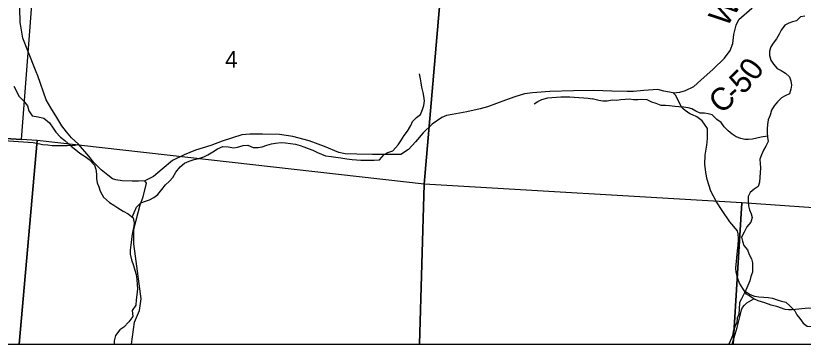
# Model space of a CAD drawing. Extents: x 5.6 to 39.6, y 0.7 to 22.7.
# Drawn here: x 9.058 to 11.039, y 14.907 to 15.732 of the extents above; entities that cross this region are included whole.
import ezdxf

# ---------------------------------------------------------------- set-up
doc = ezdxf.new("R2010")
doc.units = 0
doc.layers.add('Default', color=7, linetype='Continuous')

msp = doc.modelspace()

# ---------------------------------------------------------------- linework, layer by layer
at = {"layer": 'Default'}
for p, q in [((9.0666, 14.9074), (10.0736, 14.9074)), ((10.0736, 14.9074), (10.8627, 14.9074)), ((10.8627, 14.9074), (11.8881, 14.9074))]:
    msp.add_line(p, q, dxfattribs=at)
for points in [[(8.2518, 18.5322), (8.2518, 14.9074), (15.0518, 14.9074), (15.0518, 18.0251)], [(8.2518, 18.5322), (8.2518, 14.9074), (15.0518, 14.9074), (15.0518, 18.0251)], [(8.2518, 18.5322), (8.2518, 14.9074), (15.0518, 14.9074), (15.0518, 18.0251)], [(9.071, 15.7062), (9.0694, 15.7157), (9.0678, 15.751), (9.0715, 15.7916), (9.0832, 15.8235), (9.0994, 15.8528), (9.1107, 15.8684), (9.2839, 16.1036), (9.2922, 16.1192), (9.2982, 16.1355), (9.3024, 16.1522), (9.2985, 16.1818), (9.2893, 16.2016), (9.2741, 16.2247), (9.1605, 16.3581), (9.0759, 16.4554)], [(8.2518, 15.7856), (8.2639, 15.7623), (8.2659, 15.4721), (9.0725, 15.4217), (9.1174, 16.0112), (9.0418, 16.1995), (9.0049, 16.4106), (8.3039, 16.4383), (8.2518, 16.391)], [(10.7121, 15.5385), (10.7289, 15.5406), (10.7424, 15.5448), (10.764, 15.5548), (10.7815, 15.5703), (10.8123, 15.5978), (10.8409, 15.6257), (10.8554, 15.6454), (10.862, 15.6628), (10.8647, 15.6856), (10.8702, 15.7091), (10.8771, 15.7227), (10.9094, 15.751), (10.9487, 15.7883), (10.9807, 15.8204), (11.0062, 15.8514), (11.0204, 15.874), (11.0319, 15.8941), (11.0411, 15.9233)], [(11.0426, 15.731), (11.0319, 15.7294), (11.0223, 15.7197), (11.012, 15.7173), (11.0024, 15.7137), (10.9929, 15.709), (10.9831, 15.6959), (10.9783, 15.6858)], [(9.1097, 15.5912), (9.0885, 15.6446), (9.076, 15.6762), (9.071, 15.7062)], [(10.9783, 15.6858), (10.9716, 15.6742), (10.9634, 15.6638), (10.9572, 15.654), (10.9543, 15.6435), (10.954, 15.6325), (10.9576, 15.6206), (10.9641, 15.6106), (10.973, 15.6002), (10.9831, 15.5947), (10.9943, 15.588), (11.004, 15.5787), (11.0079, 15.5691), (11.0095, 15.558), (11.0074, 15.5479), (11.0045, 15.5365), (10.9938, 15.5311), (10.9842, 15.5264), (10.9742, 15.5164), (10.966, 15.5059), (10.9593, 15.4954), (10.9556, 15.4826), (10.9508, 15.4706), (10.9494, 15.4596), (10.948, 15.4483), (10.9482, 15.4384), (10.9494, 15.4274), (10.9503, 15.4164), (10.9451, 15.4051), (10.9389, 15.395), (10.9337, 15.3834), (10.9296, 15.3721), (10.9309, 15.3603), (10.931, 15.35), (10.9304, 15.3375), (10.9294, 15.3266), (10.9291, 15.3141), (10.9258, 15.3039), (10.9155, 15.2969), (10.9054, 15.2884), (10.9006, 15.2783), (10.9008, 15.2669), (10.9016, 15.2551), (10.9041, 15.2452), (10.908, 15.2349), (10.9101, 15.2253), (10.9068, 15.214), (10.897, 15.2021), (10.8907, 15.189), (10.884, 15.1766), (10.8864, 15.1663), (10.8899, 15.1556), (10.8984, 15.1441), (10.9031, 15.1326), (10.9085, 15.1218), (10.9113, 15.1115), (10.9114, 15.1009), (10.9112, 15.0884), (10.9075, 15.0775), (10.9042, 15.0669), (10.8994, 15.0545), (10.8946, 15.0433), (10.8887, 15.0312), (10.8835, 15.0215), (10.8784, 15.0118), (10.878, 14.9957)], [(9.2414, 15.3798), (9.216, 15.4099), (9.1982, 15.4258), (9.1853, 15.4408), (9.1742, 15.4562), (9.1616, 15.4767), (9.146, 15.5009), (9.1345, 15.5214), (9.1136, 15.5813), (9.1097, 15.5912)], [(9.351, 15.2267), (9.3562, 15.238), (9.362, 15.2516), (9.3723, 15.2621), (9.3845, 15.2665), (9.3948, 15.2702), (9.4055, 15.2761), (9.4154, 15.2832), (9.4258, 15.2956), (9.435, 15.3076), (9.4446, 15.3166), (9.4534, 15.3264), (9.4608, 15.3392), (9.4715, 15.3528), (9.4822, 15.3617), (9.4941, 15.3669), (9.5066, 15.3713), (9.5188, 15.3742), (9.5313, 15.3779), (9.5412, 15.3827), (9.5534, 15.3902), (9.5657, 15.3984), (9.5786, 15.4043), (9.5922, 15.4034), (9.6066, 15.4005), (9.6161, 15.402), (9.6298, 15.4067), (9.6419, 15.4073), (9.6555, 15.4011), (9.6676, 15.4014), (9.6779, 15.4035), (9.6897, 15.4076), (9.7011, 15.4108), (9.7113, 15.4126), (9.7258, 15.4136), (9.7367, 15.4135), (9.7489, 15.4118), (9.7613, 15.4098), (9.773, 15.4066), (9.7829, 15.4031), (9.7938, 15.3991), (9.8051, 15.3945), (9.8172, 15.3886), (9.827, 15.3851), (9.8368, 15.3808), (9.8516, 15.3787), (9.8629, 15.3775), (9.8758, 15.3758), (9.8905, 15.3734), (9.9038, 15.3713), (9.9155, 15.3704), (9.9261, 15.3699), (9.9504, 15.3696), (9.9598, 15.3699), (9.9731, 15.3709), (9.9846, 15.384), (9.9942, 15.3885), (10.0063, 15.3933), (10.0198, 15.4079), (10.0263, 15.4181), (10.0348, 15.4313), (10.0433, 15.4426), (10.0518, 15.4569), (10.0557, 15.4667), (10.0664, 15.4772), (10.076, 15.4843), (10.0814, 15.4971), (10.0849, 15.507), (10.0858, 15.5184), (10.0841, 15.5301), (10.0827, 15.54), (10.0798, 15.5526), (10.078, 15.564), (10.0762, 15.5742), (10.0737, 15.5864)], [(9.0528, 15.5557), (9.0587, 15.5446), (9.0654, 15.5305), (9.0774, 15.5186), (9.0879, 15.506), (9.0911, 15.4938), (9.099, 15.4812), (9.1145, 15.4783), (9.1288, 15.4748), (9.1427, 15.4632), (9.152, 15.4502), (9.1587, 15.4399), (9.1703, 15.4276), (9.1812, 15.4191), (9.1974, 15.4049), (9.2094, 15.3953), (9.2195, 15.3876), (9.2323, 15.3791), (9.2425, 15.371), (9.2563, 15.3575), (9.2596, 15.3469), (9.261, 15.3343), (9.2613, 15.3233), (9.263, 15.313), (9.2667, 15.3024), (9.2707, 15.2921), (9.2785, 15.2764), (9.2935, 15.2634), (9.3045, 15.2564), (9.315, 15.2498), (9.3285, 15.2417), (9.341, 15.2347), (9.353, 15.2251), (9.3562, 15.2125), (9.3546, 15.2027), (9.3522, 15.1921), (9.3498, 15.1788), (9.3489, 15.1694), (9.3477, 15.1568), (9.3456, 15.144), (9.3459, 15.1333), (9.3491, 15.1193), (9.3543, 15.1052), (9.3579, 15.0934), (9.3605, 15.0823), (9.3626, 15.0694), (9.3636, 15.0572), (9.3638, 15.0466), (9.3629, 15.0318), (9.3612, 15.0189), (9.36, 15.0053)], [(10.8747, 15.1502), (10.8752, 15.1546), (10.8757, 15.1729), (10.8749, 15.1848), (10.8734, 15.1923), (10.8541, 15.2144), (10.8348, 15.2431), (10.8209, 15.2652), (10.8064, 15.2919), (10.7973, 15.3211), (10.794, 15.3387), (10.7914, 15.3598), (10.7924, 15.3824), (10.7962, 15.4076), (10.7983, 15.4242), (10.7978, 15.4493), (10.7849, 15.4684), (10.7715, 15.4787), (10.7605, 15.4835), (10.7536, 15.4858), (10.7415, 15.4941), (10.7372, 15.4986), (10.7326, 15.5029), (10.7241, 15.5205), (10.7179, 15.5328), (10.7121, 15.5385), (10.6879, 15.5431), (10.6731, 15.5469), (10.638, 15.5446), (10.6117, 15.5419), (10.5956, 15.5419), (10.5573, 15.5429), (10.512, 15.5449), (10.4609, 15.5434), (10.4014, 15.5421), (10.3582, 15.5389), (10.3381, 15.5364), (10.3137, 15.5291), (10.2898, 15.5203), (10.2444, 15.5034), (10.2262, 15.4986), (10.193, 15.4908), (10.1554, 15.4843), (10.1417, 15.4815), (10.1296, 15.4765), (10.1058, 15.4602), (10.0827, 15.4381), (10.0634, 15.4157), (10.046, 15.3966), (10.0266, 15.3837), (9.9912, 15.3842), (9.9552, 15.3842), (9.9158, 15.385), (9.8869, 15.3855), (9.8705, 15.3893), (9.8343, 15.4041), (9.796, 15.4182), (9.7551, 15.4295), (9.7218, 15.434), (9.6787, 15.435), (9.647, 15.435), (9.6264, 15.4333), (9.5768, 15.4172), (9.549, 15.4063), (9.51, 15.3944), (9.4817, 15.383), (9.452, 15.3684), (9.4266, 15.3467), (9.4043, 15.3285), (9.383, 15.3174), (9.3671, 15.3173), (9.3508, 15.3173), (9.3258, 15.3176), (9.3097, 15.3201), (9.3017, 15.3231), (9.2892, 15.3323), (9.2732, 15.3456), (9.2546, 15.3641), (9.2414, 15.3798)], [(10.362, 15.5114), (10.3716, 15.517), (10.3811, 15.5222), (10.3963, 15.5262), (10.4065, 15.5272), (10.4183, 15.5282), (10.4289, 15.5284), (10.441, 15.5291), (10.4517, 15.5289), (10.4626, 15.528), (10.474, 15.5272), (10.4872, 15.5262), (10.4978, 15.5254), (10.5077, 15.5241)], [(10.9491, 15.43), (10.9335, 15.4274), (10.9225, 15.4246), (10.9115, 15.4225), (10.9016, 15.4216), (10.8917, 15.4218), (10.8816, 15.4243), (10.8703, 15.4284), (10.8598, 15.4351), (10.8498, 15.4433), (10.8402, 15.453), (10.8321, 15.4641), (10.8213, 15.472), (10.8098, 15.4832), (10.8, 15.4861), (10.7902, 15.4874), (10.78, 15.4873), (10.7687, 15.4925), (10.759, 15.4988), (10.7492, 15.5013), (10.7379, 15.503), (10.7258, 15.504), (10.7156, 15.5047), (10.7024, 15.5061), (10.6925, 15.5071), (10.6812, 15.5066), (10.6688, 15.5121), (10.6579, 15.5154), (10.6463, 15.521), (10.6357, 15.5224), (10.6228, 15.5215), (10.6118, 15.521), (10.6009, 15.5228), (10.5906, 15.5218), (10.5804, 15.5213), (10.5694, 15.5197), (10.558, 15.5207), (10.5455, 15.5175), (10.5345, 15.5178), (10.5247, 15.5195), (10.515, 15.5221), (10.5077, 15.5241)], [(9.0666, 14.9074), (9.1119, 15.4192), (9.0725, 15.4217), (8.2659, 15.4721), (8.2518, 15.4436)], [(8.2518, 15.4436), (8.2518, 14.9074), (9.0666, 14.9074)], [(8.967, 15.4233), (9.1014, 15.4139), (9.1188, 15.4104), (9.1255, 15.4092), (9.1387, 15.4082), (9.1497, 15.4066), (9.1562, 15.4066)], [(10.0736, 14.9074), (10.0852, 15.3096), (9.1119, 15.4192), (9.0666, 14.9074)], [(9.1562, 15.4066), (9.1582, 15.4066), (9.1692, 15.4064), (9.1797, 15.4061), (9.1877, 15.4064), (9.2009, 15.4074), (9.2073, 15.4076), (9.216, 15.4099)], [(9.3495, 14.9074), (9.3567, 14.9632), (9.3692, 14.9925), (9.3737, 15.0213), (9.3588, 15.1288), (9.3552, 15.1594), (9.3549, 15.1961), (9.3707, 15.2575), (9.3785, 15.2776), (9.3871, 15.3116), (9.383, 15.3174)], [(10.8627, 14.9074), (10.8842, 15.2625), (10.0852, 15.3096), (10.0736, 14.9074)], [(11.8881, 14.9074), (11.9086, 15.1889), (11.0648, 15.2501), (10.8842, 15.2625), (10.8627, 14.9074)], [(10.9716, 15.002), (10.9586, 15.0054), (10.942, 15.0112), (10.9259, 15.016), (10.915, 15.0214), (10.9082, 15.0257), (10.902, 15.0294), (10.896, 15.0335), (10.887, 15.047), (10.8789, 15.0608), (10.874, 15.0721), (10.8699, 15.088), (10.8692, 15.098), (10.8747, 15.1502)], [(10.8932, 15.0405), (10.9054, 15.0324), (10.9163, 15.028), (10.9268, 15.0266), (10.9401, 15.0259), (10.951, 15.0246), (10.9616, 15.0228), (10.9736, 15.0191), (10.9841, 15.0159), (10.9951, 15.013), (11.0051, 15.004), (11.0177, 14.9914)], [(10.8605, 14.9074), (10.8727, 14.949), (10.879, 14.9764), (10.8834, 14.9934), (10.8865, 14.9996), (10.8911, 15.0057), (10.8974, 15.0117), (10.915, 15.0214)], [(9.36, 15.0053), (9.3506, 14.9919), (9.3525, 14.977), (9.3421, 14.9636), (9.3297, 14.9505), (9.3197, 14.9439), (9.3085, 14.9293), (9.3056, 14.9161), (9.3054, 14.9074)], [(11.3418, 14.9074), (11.3405, 14.9084), (11.3288, 14.9162), (11.3096, 14.9309), (11.2818, 14.9518), (11.2626, 14.9638), (11.2467, 14.9748), (11.2283, 14.9791), (11.1995, 14.9822), (11.1647, 14.9872), (11.1431, 14.9924), (11.1268, 14.9949), (11.1059, 14.9965), (11.0525, 14.9977), (11.0113, 14.9939), (11.0018, 14.9935), (10.9938, 14.995), (10.9727, 15.0018), (10.9716, 15.002)], [(10.878, 14.9957), (10.8769, 14.9832), (10.8724, 14.9729), (10.8717, 14.9616), (10.8668, 14.9509), (10.8626, 14.9392), (10.8611, 14.9285), (10.8555, 14.9149), (10.8519, 14.9074)], [(11.0177, 14.9914), (11.0231, 14.9815), (11.0307, 14.9717), (11.0386, 14.9607), (11.0485, 14.9531), (11.0591, 14.9516), (11.0697, 14.9478), (11.0803, 14.9418), (11.0902, 14.9354), (11.0982, 14.9255), (11.1058, 14.9153), (11.1156, 14.9081), (11.1167, 14.9074)]]:
    msp.add_lwpolyline(points, dxfattribs=at)
for points in [[(10.0851, 16.2878), (10.169, 16.28), (10.0852, 15.3096), (9.1119, 15.4192), (9.0725, 15.4217), (9.1174, 16.0112), (9.2162, 15.8528), (9.2902, 15.796), (9.3445, 15.8093), (9.5455, 15.8584), (9.8328, 15.9813), (10.0295, 16.2307)], [(10.169, 16.28), (10.5184, 16.2529), (10.5154, 16.2914), (11.1299, 16.2192), (11.0648, 15.2501), (10.8842, 15.2625), (10.0852, 15.3096)]]:
    msp.add_lwpolyline(points, close=True, dxfattribs=at)

# ---------------------------------------------------------------- texts
for s, height, rotation, p in [('W', 0.0568, 56.6813, (10.8453, 15.7012)), ('4', 0.0418, 0, (9.5848, 15.6019)), ('0', 0.0568, 54.7698, (10.9189, 15.5655)), ('5', 0.0568, 44.5382, (10.8868, 15.5325)), ('C', 0.0568, 41.783, (10.8326, 15.4836)), ('-', 0.0568, 42.5296, (10.868, 15.5153))]:
    msp.add_text(s, height=height, rotation=rotation, dxfattribs=at).set_placement(p)

doc.saveas('drawing.dxf')
